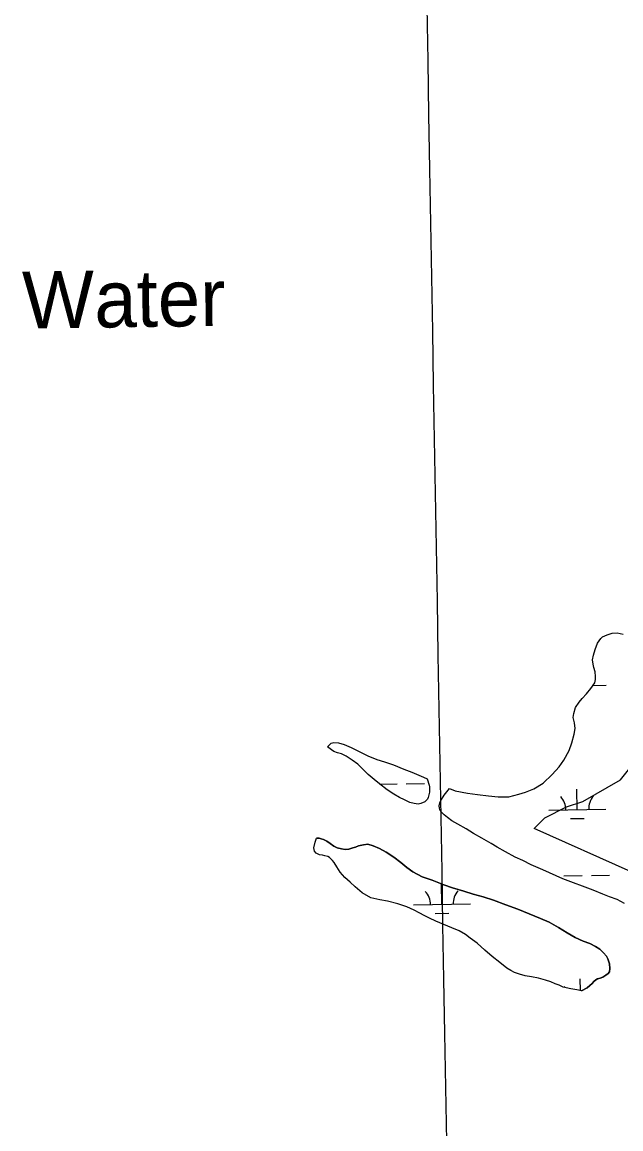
# Model space of a CAD drawing. Extents: x 3903937 to 3942190, y 260677 to 286651.
# Drawn here: x 3912627 to 3913677, y 274746 to 276686 of the extents above; entities that cross this region are included whole.
import ezdxf

# ---------------------------------------------------------------- set-up
doc = ezdxf.new("R2010")
doc.units = 0
for name, color, linetype in [('V-GRID-MAJR', 7, 'Continuous'), ('V-RIVR-IDEN', 7, 'Continuous'), ('V-SITE-VEGE', 7, 'Continuous'), ('V-TOPO-SHOR', 7, 'Continuous'), ('V-WETL-SWMP', 7, 'Continuous')]:
    doc.layers.add(name, color=color, linetype=linetype)

msp = doc.modelspace()

# ---------------------------------------------------------------- linework, layer by layer
at = {"layer": 'V-GRID-MAJR'}
msp.add_spline([(3913520.414, 266109.772), (3913415.549, 272167.798), (3913310.651, 278227.748), (3913205.754, 284287.69), (3913205.721, 284289.62200000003)], degree=3, dxfattribs=at)
at = {"layer": 'V-SITE-VEGE'}
msp.add_lwpolyline([(3913695.002, 275197.07), (3913524.772, 275272.766), (3913543.686, 275291.69), (3913581.514, 275310.613), (3913609.887, 275320.075), (3913676.089, 275357.924), (3913713.918, 275405.235)], dxfattribs=at)
at = {"layer": 'V-TOPO-SHOR'}
for points in [[(3913425.461, 275332.359), (3913444.806, 275329.787), (3913461.3850000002, 275327.978), (3913480.308, 275328.163), (3913497.616, 275332.67), (3913509.7970000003, 275336.731), (3913524.332, 275342.39400000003), (3913540.401, 275352.409), (3913556.418, 275367.55), (3913568.5100000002, 275381.075), (3913576.679, 275392.589), (3913585.975, 275409.634), (3913590.575, 275423.087), (3913594.765, 275438.11100000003), (3913596.6410000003, 275447.987), (3913595.361, 275457.832), (3913593.296, 275467.275), (3913594.4110000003, 275474.384), (3913597.46, 275485.06), (3913603.68, 275494.19), (3913609.1380000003, 275500.553), (3913616.5470000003, 275508.905), (3913624.344, 275518.049), (3913631.34, 275528.371), (3913632.075, 275533.898), (3913632.024, 275539.025), (3913631.549, 275547.301), (3913629.106, 275555.163), (3913628.264, 275560.674), (3913627.009, 275568.153), (3913628.899, 275576.452), (3913631.557, 275586.731), (3913635.79, 275597.417), (3913641.623, 275605.755), (3913644.7460000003, 275608.939), (3913652.6, 275612.17100000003), (3913661.247, 275615.016), (3913670.307, 275615.89400000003), (3913680.582, 275613.627)], [(3913162.1950000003, 275415.819), (3913168.441, 275422.11), (3913173.162, 275423.339), (3913181.681, 275423.028), (3913191.569, 275419.97000000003), (3913203.845, 275414.57), (3913216.524, 275408.385), (3913232.773, 275399.869), (3913248.9990000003, 275393.719), (3913262.0530000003, 275389.51), (3913277.878, 275384.145), (3913296.0870000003, 275376.831), (3913310.335, 275371.449), (3913330.921, 275362.977), (3913337.151, 275359.93700000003)], [(3913337.151, 275359.93700000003), (3913340.833, 275348.858), (3913341.257, 275346.083), (3913341.356, 275336.16000000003), (3913338.665, 275327.001), (3913337.501, 275324.212), (3913332.785, 275319.401), (3913326.063, 275316.55700000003), (3913321.312, 275315.32), (3913314.154, 275316.44), (3913306.595, 275318.351), (3913297.418, 275323.02400000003), (3913288.64, 275327.306), (3913278.662, 275332.766), (3913267.075, 275340.592), (3913253.4760000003, 275350.781), (3913243.8710000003, 275358.627), (3913233.862, 275367.263), (3913223.444, 275377.085), (3913215.4220000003, 275385.34500000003), (3913205.426, 275392.789), (3913195.034, 275399.832), (3913186.66, 275403.721), (3913179.8910000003, 275405.64), (3913173.522, 275407.564), (3913169.086, 275410.373), (3913162.1950000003, 275415.819)], [(3913539.784, 275200.163), (3913519.45, 275209.094), (3913505.085, 275216.49700000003), (3913491.13, 275222.711), (3913474.369, 275231.679), (3913459.992, 275240.273), (3913449.611, 275246.521), (3913433.241, 275255.891), (3913418.473, 275264.083), (3913405.294, 275271.89400000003), (3913390.923, 275280.09), (3913380.54, 275286.338), (3913372.94, 275292.22000000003), (3913366.9390000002, 275296.924), (3913362.128, 275301.643), (3913359.308, 275305.981), (3913358.489, 275308.354), (3913358.055, 275312.321), (3913358.8170000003, 275315.504), (3913359.97, 275319.485), (3913362.309, 275323.874), (3913365.045, 275328.26900000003), (3913366.605, 275331.063), (3913368.961, 275333.864), (3913376.4930000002, 275342.597)], [(3913376.4930000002, 275342.597), (3913385.967, 275338.675), (3913407.694, 275334.55), (3913425.461, 275332.359)], [(3913607.923, 274988.102), (3913599.625, 274989.993), (3913588.9590000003, 274991.858), (3913575.524, 274994.881), (3913568.79, 274997.97000000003), (3913561.272, 275000.657), (3913554.1410000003, 275004.136), (3913544.65, 275006.803), (3913532.3910000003, 275010.626), (3913520.148, 275012.478), (3913508.696, 275014.337), (3913499.201, 275017.39900000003), (3913490.497, 275020.469), (3913483.759, 275023.951), (3913477.019, 275027.827), (3913464.301, 275037.955), (3913451.188, 275048.473), (3913438.46, 275059.784), (3913424.539, 275071.87200000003), (3913412.6240000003, 275080.824), (3913404.2800000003, 275087.049), (3913393.18, 275093.251), (3913380.114, 275098.643), (3913366.257, 275104.423), (3913352.003, 275110.591), (3913340.913, 275115.609), (3913332.985, 275119.869), (3913323.077, 275124.89900000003), (3913314.359, 275129.543), (3913301.684, 275135.333), (3913285.859, 275140.701), (3913267.677, 275145.254), (3913253.8510000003, 275147.877), (3913238.44, 275151.277), (3913222.973, 275160.194), (3913211.041, 275170.723), (3913202.29, 275178.523), (3913192.7430000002, 275187.105), (3913184.37, 275196.48600000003), (3913178.7630000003, 275205.502), (3913173.954, 275213.339), (3913171.163, 275216.467), (3913165.59, 275221.933), (3913162.813, 275223.481), (3913157.677, 275224.616), (3913153.329, 275225.754), (3913148.1920000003, 275226.889), (3913142.644, 275229.594), (3913139.4560000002, 275233.11100000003), (3913138.219, 275238.62), (3913140.879, 275248.89900000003), (3913143.179, 275256.03)], [(3913607.923, 274988.102), (3913617.395, 274993.753), (3913622.521, 274997.376), (3913626.4560000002, 275000.98600000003), (3913629.595, 275004.591), (3913632.745, 275007.401), (3913635.9050000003, 275009.01900000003), (3913640.255, 275010.651), (3913645.004, 275012.283), (3913650.526, 275015.91000000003), (3913654.468, 275018.728), (3913656.823, 275021.532), (3913657.559, 275027.494), (3913656.682, 275035.821), (3913654.216, 275044.531), (3913651.791, 275048.875), (3913646.176, 275054.773), (3913639.762, 275061.06200000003), (3913632.571, 275065.756), (3913622.591, 275071.216), (3913610.6410000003, 275075.466), (3913596.686, 275081.68200000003), (3913582.71, 275089.882), (3913567.5330000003, 275099.262), (3913551.163, 275108.629), (3913536.014, 275115.23), (3913516.085, 275123.371), (3913496.156, 275131.514), (3913475.039, 275139.24700000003), (3913453.5270000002, 275146.976), (3913435.207, 275152.751), (3913417.693, 275157.74), (3913401.366, 275162.741), (3913381.46, 275168.503), (3913366.321, 275173.911), (3913345.597, 275182.04600000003), (3913328.468, 275188.231), (3913311.7090000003, 275196.8), (3913301.315, 275204.24), (3913290.909, 275212.87200000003), (3913278.511, 275222.279), (3913264.924, 275231.278), (3913253.3510000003, 275237.514), (3913242.583, 275242.57), (3913233.029, 275245.255), (3913225.492, 275244.389), (3913216.7800000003, 275242.319), (3913211.242, 275240.279), (3913206.491, 275239.042), (3913199.765, 275236.594), (3913193.4220000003, 275235.738), (3913187.059, 275236.867), (3913179.4960000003, 275238.778), (3913173.512, 275241.895), (3913167.1180000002, 275246.2), (3913161.1210000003, 275250.506), (3913155.1350000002, 275253.626), (3913151.154, 275254.777), (3913147.5700000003, 275255.934), (3913144.791, 275255.905), (3913143.179, 275256.03)], [(3913683.279, 275141.223), (3913670.506, 275148.246), (3913656.561, 275153.26900000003), (3913645.4020000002, 275157.925), (3913628.2660000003, 275164.505), (3913609.539, 275171.468), (3913593.9990000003, 275177.27), (3913574.873, 275184.626), (3913539.784, 275200.163)]]:
    msp.add_lwpolyline(points, dxfattribs=at)
at = {"layer": 'V-WETL-SWMP'}
for p, q in [((3913627.9962048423, 275523.43799402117), (3913651.1604901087, 275523.8457255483)), ((3913254.0784239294, 275350.3296029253), (3913284.2400314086, 275350.86049943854)), ((3913300.237553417, 275351.14208352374), (3913332.232597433, 275351.70525169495)), ((3913600.4002057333, 275305.67560604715), (3913599.7666415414, 275341.6700305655)), ((3913550.4079494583, 275304.7956557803), (3913650.3924620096, 275306.555556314)), ((3913588.673634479, 275290.0358078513), (3913612.6699174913, 275290.45818397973)), ((3913625.0201951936, 275190.65908024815), (3913657.01523921, 275191.22224841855)), ((3913362.8140589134, 275139.6066063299), (3913362.1816439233, 275175.53574170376)), ((3913577.0276291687, 275189.81432799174), (3913609.0226731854, 275190.37749616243)), ((3913312.821802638, 275138.7266560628), (3913412.806315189, 275140.48655659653)), ((3913351.0874876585, 275123.9668081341), (3913375.083770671, 275124.38918426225)), ((3913605.982271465, 274988.54397818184), (3913605.621390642, 275009.0465534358))]:
    msp.add_line(p, q, dxfattribs=at)
for points in [[(3913359.308, 275305.981), (3913358.49, 275308.355), (3913358.055, 275312.321), (3913358.8170000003, 275315.504), (3913359.969, 275319.485), (3913362.308, 275323.875), (3913365.044, 275328.26900000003), (3913366.605, 275331.063), (3913368.96, 275333.865), (3913376.494, 275342.596), (3913385.968, 275338.674), (3913407.6950000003, 275334.55), (3913425.46, 275332.358), (3913444.806, 275329.787), (3913461.3850000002, 275327.978), (3913480.309, 275328.163), (3913497.615, 275332.67), (3913509.798, 275336.732), (3913524.332, 275342.39400000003), (3913540.401, 275352.409), (3913556.419, 275367.55), (3913568.5100000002, 275381.074), (3913576.6780000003, 275392.589), (3913585.974, 275409.635), (3913590.574, 275423.087), (3913594.765, 275438.11100000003), (3913596.64, 275447.987), (3913595.36, 275457.832), (3913593.296, 275467.276), (3913594.41, 275474.384), (3913597.46, 275485.06), (3913603.679, 275494.19), (3913609.137, 275500.552), (3913616.5470000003, 275508.905), (3913624.344, 275518.05), (3913631.34, 275528.371), (3913632.075, 275533.898), (3913632.025, 275539.02400000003), (3913631.549, 275547.3), (3913629.106, 275555.162), (3913628.264, 275560.674), (3913627.008, 275568.153), (3913628.898, 275576.452), (3913631.558, 275586.73), (3913635.79, 275597.418), (3913641.623, 275605.755), (3913644.747, 275608.94), (3913652.6010000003, 275612.172), (3913661.248, 275615.016), (3913670.308, 275615.89400000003), (3913680.582, 275613.628)], [(3913683.279, 275141.224), (3913670.506, 275148.245), (3913656.562, 275153.26900000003), (3913645.401, 275157.924), (3913628.2660000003, 275164.505), (3913609.539, 275171.468), (3913593.9990000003, 275177.27), (3913574.872, 275184.626), (3913539.784, 275200.162), (3913519.45, 275209.094), (3913505.086, 275216.49700000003), (3913491.13, 275222.712), (3913474.369, 275231.679), (3913459.9930000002, 275240.272), (3913449.61, 275246.522), (3913433.242, 275255.89), (3913418.473, 275264.082), (3913405.295, 275271.893), (3913390.924, 275280.089), (3913380.541, 275286.339), (3913372.94, 275292.22000000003), (3913366.9390000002, 275296.925), (3913362.129, 275301.642), (3913359.308, 275305.981)], [(3913607.923, 274988.102), (3913599.6240000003, 274989.992), (3913588.9590000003, 274991.859), (3913575.523, 274994.882), (3913568.79, 274997.97000000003), (3913561.272, 275000.657), (3913554.14, 275004.136), (3913544.651, 275006.803), (3913532.39, 275010.626), (3913520.148, 275012.478), (3913508.6950000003, 275014.337), (3913499.202, 275017.39900000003), (3913490.497, 275020.468), (3913483.7600000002, 275023.951), (3913477.019, 275027.828), (3913464.302, 275037.955), (3913451.187, 275048.473), (3913438.4590000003, 275059.784), (3913424.54, 275071.871), (3913412.623, 275080.82300000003), (3913404.281, 275087.05), (3913393.18, 275093.251), (3913380.115, 275098.643), (3913366.258, 275104.422), (3913352.003, 275110.591), (3913340.913, 275115.609), (3913332.985, 275119.869), (3913323.078, 275124.898), (3913314.358, 275129.544), (3913301.684, 275135.33400000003), (3913285.859, 275140.7), (3913267.677, 275145.254), (3913253.85, 275147.878), (3913238.4390000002, 275151.276), (3913222.974, 275160.194), (3913211.042, 275170.723), (3913202.291, 275178.52400000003), (3913192.7430000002, 275187.105), (3913184.3710000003, 275196.48600000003), (3913178.7630000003, 275205.501), (3913173.954, 275213.34), (3913171.163, 275216.467), (3913165.59, 275221.93200000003), (3913162.8140000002, 275223.482), (3913157.677, 275224.615), (3913153.329, 275225.755), (3913148.1920000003, 275226.888), (3913142.645, 275229.594), (3913139.4560000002, 275233.11100000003), (3913138.219, 275238.62), (3913140.879, 275248.898), (3913143.179, 275256.03), (3913144.791, 275255.906), (3913147.5700000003, 275255.933), (3913151.154, 275254.777), (3913155.1350000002, 275253.625), (3913161.1210000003, 275250.507), (3913167.1180000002, 275246.199), (3913173.512, 275241.895), (3913179.497, 275238.778), (3913187.059, 275236.867), (3913193.4220000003, 275235.738), (3913199.765, 275236.594), (3913206.49, 275239.042), (3913211.242, 275240.279), (3913216.7800000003, 275242.318), (3913225.4930000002, 275244.389), (3913233.028, 275245.256), (3913242.582, 275242.571), (3913253.35, 275237.515), (3913264.924, 275231.277), (3913278.5100000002, 275222.279), (3913290.909, 275212.873), (3913301.315, 275204.241), (3913311.7090000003, 275196.799), (3913328.467, 275188.23), (3913345.598, 275182.045), (3913366.321, 275173.911), (3913381.46, 275168.502), (3913401.366, 275162.742), (3913417.6920000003, 275157.741), (3913435.208, 275152.751), (3913453.526, 275146.976), (3913475.039, 275139.246), (3913496.156, 275131.513), (3913516.085, 275123.371), (3913536.014, 275115.23), (3913551.164, 275108.629), (3913567.5330000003, 275099.261), (3913582.71, 275089.882), (3913596.685, 275081.68200000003), (3913610.6410000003, 275075.467), (3913622.592, 275071.217), (3913632.5700000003, 275065.757), (3913639.762, 275061.063), (3913646.176, 275054.77400000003), (3913651.791, 275048.874), (3913654.216, 275044.531), (3913656.683, 275035.821), (3913657.558, 275027.493), (3913656.823, 275021.531)], [(3913656.823, 275021.531), (3913654.468, 275018.729), (3913650.526, 275015.911), (3913645.004, 275012.284), (3913640.256, 275010.65), (3913635.9050000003, 275009.01900000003), (3913632.745, 275007.401), (3913629.596, 275004.591), (3913626.4560000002, 275000.987), (3913622.521, 274997.376), (3913617.395, 274993.753), (3913607.923, 274988.102)]]:
    msp.add_lwpolyline(points, dxfattribs=at)
msp.add_lwpolyline([(3913162.194, 275415.818), (3913168.441, 275422.11), (3913173.1610000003, 275423.339), (3913181.681, 275423.028), (3913191.568, 275419.97000000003), (3913203.844, 275414.57), (3913216.523, 275408.385), (3913232.773, 275399.87), (3913248.9990000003, 275393.719), (3913262.0530000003, 275389.51), (3913277.877, 275384.14400000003), (3913296.0870000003, 275376.831), (3913310.335, 275371.45), (3913330.921, 275362.977), (3913337.1520000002, 275359.93700000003), (3913340.833, 275348.857), (3913341.258, 275346.082), (3913341.355, 275336.159), (3913338.665, 275327.001), (3913337.502, 275324.211), (3913332.785, 275319.401), (3913326.0640000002, 275316.556), (3913321.312, 275315.319), (3913314.1550000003, 275316.44), (3913306.594, 275318.351), (3913297.417, 275323.025), (3913288.6410000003, 275327.306), (3913278.663, 275332.766), (3913267.074, 275340.592), (3913253.4760000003, 275350.781), (3913243.8710000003, 275358.627), (3913233.862, 275367.263), (3913223.444, 275377.086), (3913215.423, 275385.344), (3913205.426, 275392.789), (3913195.035, 275399.833), (3913186.66, 275403.721), (3913179.892, 275405.64), (3913173.522, 275407.563), (3913169.0870000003, 275410.373)], close=True, dxfattribs=at)
for centre, radius, start, end in [((3913545.157469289, 275305.17811496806), 35.24628790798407, 0.23658072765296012, 41.78023906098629), ((3913655.6262300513, 275307.1225564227), 35.24628790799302, 140.23657772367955, 181.78023605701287), ((3913307.5713224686, 275139.1091152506), 35.24628790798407, 0.23658072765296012, 41.78023906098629), ((3913418.0400832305, 275141.0535567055), 35.24628790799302, 140.23657772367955, 181.78023605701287), ((3913551.0122183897, 274972.5546378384), 35.24628790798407, 37.73364659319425, 41.78023906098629)]:
    msp.add_arc(centre, radius, start, end, dxfattribs=at)

# ---------------------------------------------------------------- texts
at = {"layer": 'V-RIVR-IDEN'}
msp.add_text('Water', height=99.99980199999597, rotation=0.8107055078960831, dxfattribs=at).set_placement((3912627.564705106, 276148.90167697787))

doc.saveas('drawing.dxf')
